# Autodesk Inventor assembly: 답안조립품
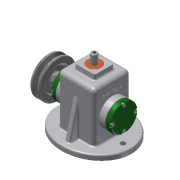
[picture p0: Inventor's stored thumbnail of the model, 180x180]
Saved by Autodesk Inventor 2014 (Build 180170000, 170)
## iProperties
Created: 2017-07
Part Number: 답안조립품
Document SubType Name: Assembly
Designer: user
Author: user
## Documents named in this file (16)
- C:\Users\user\Desktop\470707V1002\답안조립품.iam
- C:\Users\user\Desktop\470707V1002\V벨트풀리.ipt
- C:\Users\user\Desktop\470707V1002\고정핀 1.2 x  8.ipt
- C:\Users\user\Desktop\470707V1002\뒤커버.ipt
- C:\Users\user\Desktop\470707V1002\링크.ipt
- C:\Users\user\Desktop\470707V1002\멈춤나사 M3x8.ipt
- C:\Users\user\Desktop\470707V1002\베어링 12 x 32 x 10.ipt
- C:\Users\user\Desktop\470707V1002\본체.ipt
- C:\Users\user\Desktop\470707V1002\볼트 M4 x 12.ipt
- C:\Users\user\Desktop\470707V1002\부시.ipt
- C:\Users\user\Desktop\470707V1002\슬라이드.ipt
- C:\Users\user\Desktop\470707V1002\앞커버.ipt
- C:\Users\user\Desktop\470707V1002\오일실 12 25 7.ipt
- C:\Users\user\Desktop\470707V1002\키 4 x 4 x 10.ipt
- C:\Users\user\Desktop\470707V1002\편심축.ipt
- C:\Users\user\Desktop\470707V1002\핀 5 x 18.ipt
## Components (3 placed, 3 different names)
1. V벨트풀리:1 — Insert:6, Mate:2, Mate:5
2. 고정핀 1.2 x  8:1 — Mate:10
3. 핀 5 x 18:1 — Insert:14, Mate:8, Mate:10
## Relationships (6: Mate 4, Insert 2)
- Insert:6: V벨트풀리:1
- Mate:2: V벨트풀리:1
- Mate:5: V벨트풀리:1
- Insert:14: 핀 5 x 18:1
- Mate:8: 핀 5 x 18:1
- Mate:10: 고정핀 1.2 x  8:1 ↔ 핀 5 x 18:1
